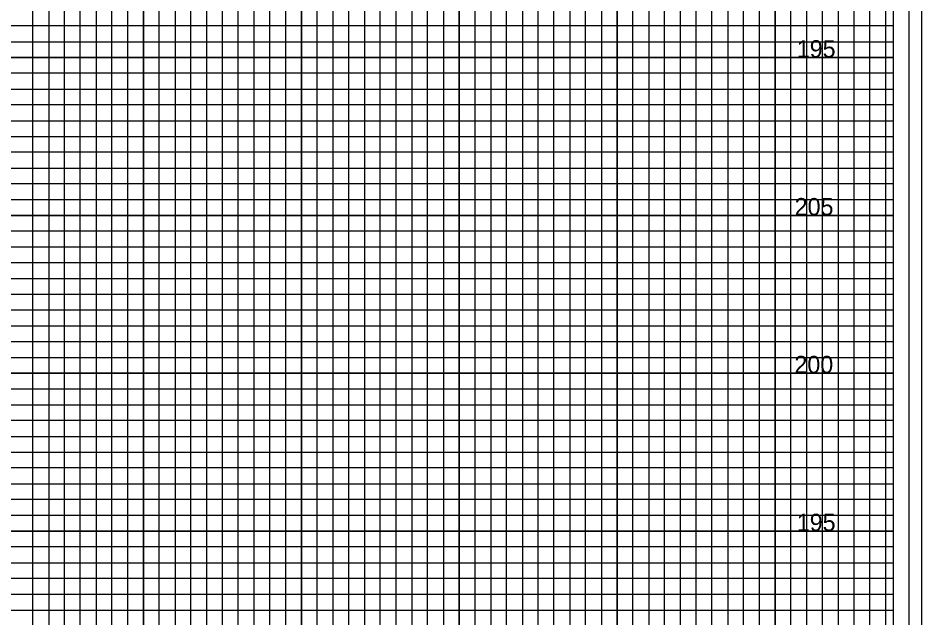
# Model space of a CAD drawing. Extents: x -4 to 103, y -2 to 351.
# Drawn here: x 74.78 to 103.4, y 103.08 to 122.08 of the extents above; entities that cross this region are included whole.
import ezdxf

# ---------------------------------------------------------------- set-up
doc = ezdxf.new("R2010")
doc.units = 0
for name, color, linetype in [('Old_Level_10', 7, 'Continuous'), ('Old_Level_4', 7, 'Continuous'), ('Old_Level_5', 7, 'Continuous'), ('Old_Level_6', 7, 'Continuous'), ('Old_Level_8', 7, 'Continuous'), ('Prop XS Finish Grade', 7, 'Continuous'), ('Prop XS SE Text', 7, 'Continuous')]:
    doc.layers.add(name, color=color, linetype=linetype)

msp = doc.modelspace()

# ---------------------------------------------------------------- linework, layer by layer
at = {"layer": 'Old_Level_10'}
for p, q in [((91.25, 70.825), (91.25, 134.25)), ((93.75, 70.825), (93.75, 134.25)), ((96.25, 70.825), (96.25, 134.25)), ((98.75, 70.825), (98.75, 134.25)), ((101.25, 70.825), (101.25, 134.25)), ((76.25, 70.825), (76.25, 132.825)), ((78.75, 70.825), (78.75, 132.825)), ((81.25, 70.825), (81.25, 132.825)), ((83.75, 70.825), (83.75, 132.825)), ((86.25, 70.825), (86.25, 132.825)), ((88.75, 70.825), (88.75, 132.825)), ((0, 120.825), (102.5, 120.825)), ((0, 118.325), (102.5, 118.325)), ((0, 115.825), (102.5, 115.825)), ((0, 113.325), (102.5, 113.325)), ((0, 110.825), (102.5, 110.825)), ((0, 108.325), (102.5, 108.325)), ((0, 105.825), (102.5, 105.825)), ((0, 103.325), (102.5, 103.325))]:
    msp.add_line(p, q, dxfattribs=at)
at = {"layer": 'Old_Level_4'}
for points in [[(90.25, 70.825), (90.25, 134.25), (90.75, 134.25), (90.75, 70.825)], [(91.75, 70.825), (91.75, 134.25), (92.25, 134.25), (92.25, 70.825)], [(92.75, 70.825), (92.75, 134.25), (93.25, 134.25), (93.25, 70.825)], [(94.25, 70.825), (94.25, 134.25), (94.75, 134.25), (94.75, 70.825)], [(95.25, 70.825), (95.25, 134.25), (95.75, 134.25), (95.75, 70.825)], [(96.75, 70.825), (96.75, 134.25), (97.25, 134.25), (97.25, 70.825)], [(97.75, 70.825), (97.75, 134.25), (98.25, 134.25), (98.25, 70.825)], [(99.25, 70.825), (99.25, 134.25), (99.75, 134.25), (99.75, 70.825)], [(100.25, 70.825), (100.25, 134.25)], [(100.25, 134.25), (100.75, 134.25), (100.75, 70.825), (101.75, 70.825), (101.75, 134.25), (102.25, 134.25), (102.25, 70.825)], [(75.25, 70.825), (75.25, 132.825), (75.75, 132.825), (75.75, 70.825)], [(76.75, 70.825), (76.75, 132.825), (77.25, 132.825), (77.25, 70.825)], [(77.75, 70.825), (77.75, 132.825), (78.25, 132.825), (78.25, 70.825)], [(79.25, 70.825), (79.25, 132.825), (79.75, 132.825), (79.75, 70.825)], [(80.25, 70.825), (80.25, 132.825), (80.75, 132.825), (80.75, 70.825)], [(81.75, 70.825), (81.75, 132.825), (82.25, 132.825), (82.25, 70.825)], [(82.75, 70.825), (82.75, 132.825), (83.25, 132.825), (83.25, 70.825)], [(84.25, 70.825), (84.25, 132.825), (84.75, 132.825), (84.75, 70.825)], [(85.25, 70.825), (85.25, 132.825), (85.75, 132.825), (85.75, 70.825)], [(86.75, 70.825), (86.75, 132.825), (87.25, 132.825), (87.25, 70.825)], [(87.75, 70.825), (87.75, 132.825), (88.25, 132.825), (88.25, 70.825)], [(89.25, 70.825), (89.25, 132.825), (89.75, 132.825), (89.75, 70.825)], [(0, 121.325), (102.5, 121.325), (102.5, 121.825), (0, 121.825)], [(0, 119.825), (102.5, 119.825), (102.5, 120.325), (0, 120.325)], [(0, 118.825), (102.5, 118.825), (102.5, 119.325), (0, 119.325)], [(0, 117.325), (102.5, 117.325), (102.5, 117.825), (0, 117.825)], [(0, 116.325), (102.5, 116.325), (102.5, 116.825), (0, 116.825)], [(0, 114.825), (102.5, 114.825), (102.5, 115.325), (0, 115.325)], [(0, 113.825), (102.5, 113.825), (102.5, 114.325), (0, 114.325)], [(0, 112.325), (102.5, 112.325), (102.5, 112.825), (0, 112.825)], [(0, 111.325), (102.5, 111.325), (102.5, 111.825), (0, 111.825)], [(0, 109.825), (102.5, 109.825), (102.5, 110.325), (0, 110.325)], [(0, 108.825), (102.5, 108.825), (102.5, 109.325), (0, 109.325)], [(0, 107.325), (102.5, 107.325), (102.5, 107.825), (0, 107.825)], [(0, 106.325), (102.5, 106.325), (102.5, 106.825), (0, 106.825)], [(0, 104.825), (102.5, 104.825), (102.5, 105.325), (0, 105.325)], [(0, 103.825), (102.5, 103.825), (102.5, 104.325), (0, 104.325)]]:
    msp.add_lwpolyline(points, dxfattribs=at)
at = {"layer": 'Old_Level_5'}
msp.add_lwpolyline([(103.4, 138.225), (-3.5, 138.225), (-3.5, 68.4), (103.4, 68.4)], close=True, dxfattribs=at)
at = {"layer": 'Old_Level_6'}
msp.add_lwpolyline([(102.5, 135.825), (0, 135.825), (0, 70.825), (102.5, 70.825)], close=True, dxfattribs=at)
at = {"layer": 'Old_Level_8'}
for points in [[(91.25, 70.825), (91.25, 134.25), (93.75, 134.25), (93.75, 70.825)], [(96.25, 70.825), (96.25, 134.25), (98.75, 134.25), (98.75, 70.825)], [(101.25, 70.825), (101.25, 134.25)], [(76.25, 70.825), (76.25, 132.825), (78.75, 132.825), (78.75, 70.825)], [(81.25, 70.825), (81.25, 132.825), (83.75, 132.825), (83.75, 70.825)], [(86.25, 70.825), (86.25, 132.825), (88.75, 132.825), (88.75, 70.825)], [(0, 118.325), (102.5, 118.325), (102.5, 120.825), (0, 120.825)], [(0, 113.325), (102.5, 113.325), (102.5, 115.825), (0, 115.825)], [(0, 108.325), (102.5, 108.325), (102.5, 110.825), (0, 110.825)], [(0, 103.325), (102.5, 103.325), (102.5, 105.825), (0, 105.825)]]:
    msp.add_lwpolyline(points, dxfattribs=at)
at = {"layer": 'Prop XS SE Text'}
msp.add_lwpolyline([(103, 136.825), (-2.8, 136.825), (-2.8, 69.825), (103, 69.825)], close=True, dxfattribs=at)

# ---------------------------------------------------------------- texts
at = {"layer": 'Prop XS Finish Grade'}
for s, p in [('195', (99.4383, 120.825)), ('205', (99.3724, 115.825)), ('200', (99.3638, 110.825)), ('195', (99.4383, 105.825))]:
    msp.add_text(s, height=0.55, dxfattribs=at).set_placement(p)

doc.saveas('drawing.dxf')
